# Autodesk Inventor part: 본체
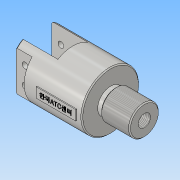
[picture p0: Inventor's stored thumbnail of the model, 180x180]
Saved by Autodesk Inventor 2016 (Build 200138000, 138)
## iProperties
Created: 2019-02
Part Number: 본체
Material: 알루미늄 6061
Document SubType Name: Modeling
Designer: Administrator
Density: 2.7 g/cm^3
Appearance: 알루미늄 - 평지
Mass: 345.633 g
Surface Area: 298.06 cm^2
Volume: 128.012 cm^3
Author: Administrator
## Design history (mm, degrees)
sketch "스케치1"
  geometry: L1 (0, 0)-(108, 0); L2 (108, 0)-(108, 15); L3 (108, 15)-(79, 15); L4 (79, 15)-(79, 13); L5 (79, 13)-(74, 13); L6 (74, 13)-(74, 29); L7 (74, 29)-(0, 29); L8 (0, 29)-(0, 0)
  constraints: 16 end point, 6 perpendicular, 1 horizontal, 1 vertical
  dimensions: "d0" = 108 distance of L1.start L1.end; "d1" = 5 distance of L4.end L5.end; "d2" = 34 distance between parallel lines of L6 L2; "d3" = 58 diameter of L7 L1; "d4" = 26 diameter of L5 L1; "d5" = 30 diameter of L3 L1
revolve "회전1" sketch "스케치1" stored, may be unused: angle "d6" = 90 deg
sketch "스케치2"
  geometry: L1 (-15, 32.374)-(15, 32.374); L2 (15, 32.374)-(15, -32.374); L3 (15, -32.374)-(-15, -32.374); L4 (-15, -32.374)-(-15, 32.374); L5 (-22, 39.782)-(22, 39.782); L6 (22, 39.782)-(22, -39.782); L7 (22, -39.782)-(-22, -39.782); L8 (-22, -39.782)-(-22, 39.782); C1 r 29 at (0, 0) reference; 4 further points
  constraints: 16 end point, 4 midpoint, 4 parallel, 2 horizontal, 2 horizontal alignment, 2 perpendicular, 2 vertical alignment
  dimensions: "d7" = 30 distance of L2.end L3.end; "d8" = 44 distance of L5.start L5.end
extrude "돌출1" cut sketch "스케치2" distance "d9" = 36; taper "d10" = 0 deg
sketch "스케치4"
  geometry: L1 (74, -29)-(74, 29) reference; L2 (0, 24.819)-(36, 24.819) reference; L3 (36, 24.819)-(36, 24.819) reference; L4 (36, 24.819)-(0, 24.819) reference; L5 (0, -24.819)-(36, -24.819) reference; L6 (36, -24.819)-(36, -24.819) reference; L7 (36, -24.819)-(0, -24.819) reference; L8 (79, -15)-(79, 15) reference; L9 (108, -15)-(108, 15) reference; L10 (36, -24.819)-(36, 24.819) reference; L11 (36, 0)-(108, 0); L12 (36, 14)-(38.65, 14); L13 (38.65, 14)-(38.65, 17); L14 (38.65, 17)-(43.35, 17); L15 (43.35, 17)-(43.35, 14); L16 (43.35, 14)-(47.65, 14); L17 (47.65, 14)-(47.65, 17); L18 (47.65, 17)-(52.35, 17); L19 (52.35, 17)-(52.35, 14); L20 (52.35, 14)-(56, 14); L21 (56, 14)-(56, 16); L22 (56, 16)-(63, 16); L23 (63, 16)-(63, 4); L24 (41, 17)-(41, 0); L25 (50, 17)-(50, 0); L26 (36, 14)-(36, 0); L27 (63, 4)-(108, 4); L28 (0, 24.819)-(0, -24.819) reference; L29 (0, -24.819)-(0, 24.819) reference; 1 further point
  constraints: 34 end point, 10 point on line, 9 perpendicular, 4 midpoint, 2 horizontal, 2 vertical
  dimensions: "d14" = 28 diameter of L12 L11; "d15" = 34 diameter of L14 L11; "d16" = 32 diameter of L22 L11; "d17" = 4.7 distance of L13.end L14.end; "d18" = 4.7 distance of L17.end L18.end; "d19" = 5 distance between parallel lines of L10 L24; "d20" = 9 distance between parallel lines of L24 L25; "d21" = 7 distance of L21.end L22.end; "d22" = 20 distance between parallel lines of L10 L21; "d23" = 8 diameter of L27 L11
revolve "회전2" sketch "스케치4" stored, may be unused: angle "d24" = 90 deg
sketch "스케치5"
  geometry: L1 (0, -40.6)-(0, 40.6) reference; C1 r 4 at (0, 0) reference; C2 r 15 at (0, 0) reference; 1 further point
  constraints: 1 coincident
hole "구멍1" sketch "스케치5" at (0, 0) diameter "d25" = 12.376; stored, may be unused: countersink angle "d29" = 90 deg, drill point angle "d31" = 118 deg; dims "d26" = 18, "d27" = 4, "d28" = 2, "d30" = 22
sketch "스케치6"
  geometry: L1 (-22.992, 36.295)-(21.008, 36.295); L2 (21.008, 19.992)-(21.008, -19.992); L3 (21.008, -37.953)-(-22.992, -37.953); L4 (-22.992, -17.673)-(-22.992, 17.673); L5 (-15, -24.819)-(-15, 24.819) reference; C1 r 4 at (0, 0) reference; A1 r 29 centre (0, 0) between (15, -24.819) and (15, 24.819) reference; A2 r 29 centre (0, 0) between (-15, 24.819) and (-15, -24.819) reference; 1 further point
  constraints: 8 end point, 4 point on circle, 2 parallel, 1 horizontal, 1 midpoint, 1 perpendicular
  dimensions: "d32" = 44 distance of L3.start L3.end
extrude "돌출3" cut sketch "스케치6" distance "d33" = 16; taper "d34" = 0 deg
fillet "모깎기1" dims "d35" = 0.8
sketch "스케치7"
  geometry: L1 (0, 0)-(0, 39.984) reference; L2 (0, 0)-(0, 39.984) reference; L3 (16, 0)-(0, 0) reference; L4 (16, 0)-(16, 39.984) reference; L5 (0, 39.984)-(16, 39.984) reference; L6 (0, 19.992)-(8.632, 19.992); C1 r 3 at (9, 28.992); C2 r 3 at (9, 10.992)
  constraints: 2 centre point, 2 end point, 1 horizontal, 1 vertical alignment
  dimensions: "d36" = 6 diameter of C1; "d37" = 6 diameter of C2; "d38" = 9 distance from line of C1.centre L6; "d39" = 9 distance from line of L6 C2.centre; "d40" = 9 distance from line of L1 C2.centre
extrude "돌출4" cut sketch "스케치7" distance "d41" = 100; taper "d42" = 0 deg
node "작업 평면1"
sketch "스케치8"
  geometry: L1 (42, -15)-(42, 15) reference; L2 (71, -15)-(71, 15) reference; L3 (-21, 17.673)-(-37, 17.673) reference; L4 (-37, 17.673)-(-37, 24.819) reference; L5 (-37, 24.819)-(-1, 24.819) reference; L6 (-1, 24.819)-(-1, 24.819) reference; L7 (-1, 24.819)-(-37, 24.819) reference; L8 (-37, 24.819)-(-37, 19.992) reference; L9 (-37, 19.992)-(-21, 19.992) reference; L10 (-21, 19.992)-(-21, -19.992) reference; L11 (-21, -19.992)-(-37, -19.992) reference; L12 (-37, -19.992)-(-37, -24.819) reference; L13 (-37, -24.819)-(-1, -24.819) reference; L14 (-1, -24.819)-(-1, -24.819) reference; L15 (-1, -24.819)-(-37, -24.819) reference; L16 (-37, -24.819)-(-37, -17.673) reference; L17 (-37, -17.673)-(-21, -17.673) reference; L18 (-21, -17.673)-(-21, 17.673) reference; L19 (37, -29)-(37, 29) reference; L20 (-8, 5)-(32, 5); L21 (32, 5)-(32, -5); L22 (32, -5)-(-8, -5); L23 (-8, -5)-(-8, 5); 3 further points
  constraints: 8 end point, 2 midpoint, 2 parallel, 1 horizontal, 1 horizontal alignment, 1 perpendicular
  dimensions: "d43" = 40 distance of L21.end L22.end; "d44" = 10 distance of L20.end L21.end; "d45" = 5 distance between parallel lines of L19 L21
extrude "돌출5" join sketch "스케치8" distance "d46" = 1; taper "d47" = 0 deg
sketch "스케치10"
  geometry: L1 (32, 5)-(-8, 5) reference; L2 (-8, 5)-(-8, -5) reference; L3 (-7.998, 5.054)-(31.998, 5.054); L4 (31.998, 5.054)-(31.998, -5.054); L5 (31.998, -5.054)-(-7.998, -5.054); L6 (-7.998, -5.054)-(-7.998, 5.054); 5 further points
  constraints: 4 midpoint, 1 horizontal alignment, 1 vertical alignment, 2 other
feature "엠보싱1" sketch "스케치10" dims "d0" = 108, "d1" = 5, "d2" = 34, "d3" = 58, "d4" = 26, "d5" = 30, "d48" = 0.5, "d49" = 0
chamfer "모따기1" distance "d50" = 1; stored, may be unused: second distance "d51" = 2, angle "d52" = 45 deg
feature "스레드1" dims "d53" = 10, "d54" = 0
chamfer "모따기2" distance "d55" = 1; stored, may be unused: second distance "d56" = 2, angle "d57" = 45 deg
sketch "스케치9"
  geometry: L1 (15, 24.819)-(15, -24.819) reference; L2 (-15, -24.819)-(-15, 24.819) reference; C1 r 14 at (0, 0) reference; A1 r 29 centre (0, 0) between (-15, -24.819) and (15, -24.819) reference; A2 r 29 centre (0, 0) between (15, 24.819) and (-15, 24.819) reference
node "솔리드1"
node "투영된 루프4"
node "투영된 루프5"
node "투영된 루프6"
node "투영된 루프7"
node "투영된 루프8"
node "투영된 루프9"
node "투영된 루프10"
